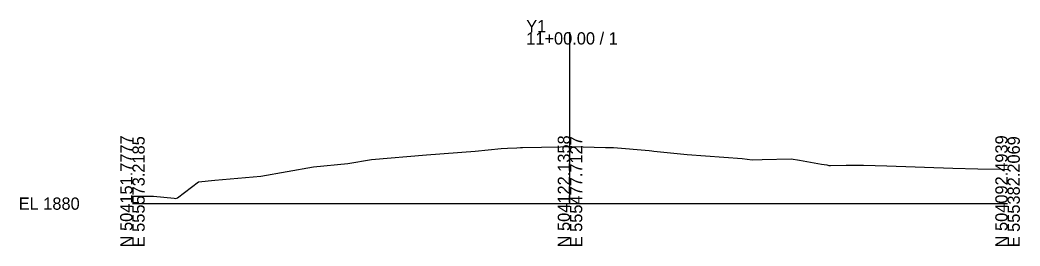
# Model space of a CAD drawing. Extents: x -26 to 203, y -10 to 5015.
# Drawn here: x -25.7 to 202.8, y 990.3 to 1042 of the extents above; entities that cross this region are included whole.
import ezdxf

# ---------------------------------------------------------------- set-up
doc = ezdxf.new("R2010")
doc.units = 0
doc.layers.add('Exist Cross Section Cell', color=7, linetype='Continuous')
doc.layers.add('Exist XS Ground Line', color=7, linetype='Continuous')

msp = doc.modelspace()

# ---------------------------------------------------------------- linework, layer by layer
at = {"layer": 'Exist Cross Section Cell'}
for p, q in [((100, 1000), (100, 1039.17)), ((0, 1000), (100, 1000)), ((100, 1000), (200, 1000))]:
    msp.add_line(p, q, dxfattribs=at)
at = {"layer": 'Exist XS Ground Line'}
for p, q in [((78.3, 1011.97), (84.28, 1012.56)), ((84.28, 1012.56), (85.71, 1012.66)), ((85.71, 1012.66), (87.83, 1012.76)), ((87.83, 1012.76), (88.72, 1012.8)), ((88.72, 1012.8), (89.18, 1012.84)), ((89.18, 1012.84), (97.85, 1012.98)), ((97.85, 1012.98), (100, 1013.05)), ((100, 1013.05), (100.39, 1013.06)), ((100.39, 1013.06), (108.14, 1012.85)), ((108.14, 1012.85), (109.96, 1012.79)), ((109.96, 1012.79), (118.13, 1012.11)), ((54.62, 1010.06), (67.24, 1011.16)), ((67.24, 1011.16), (78.3, 1011.97)), ((118.13, 1012.11), (118.69, 1012.07)), ((118.69, 1012.07), (119.17, 1012.02)), ((119.17, 1012.02), (126.78, 1011.24)), ((126.78, 1011.24), (139.32, 1010.33)), ((139.32, 1010.33), (141.66, 1010.03)), ((143.9, 1010.09), (150.54, 1010.23)), ((150.54, 1010.23), (152.42, 1009.95)), ((29.35, 1006.31), (41.39, 1008.4)), ((41.39, 1008.4), (49.22, 1009.16)), ((49.22, 1009.16), (54.62, 1010.06)), ((141.66, 1010.03), (143.9, 1010.09)), ((152.42, 1009.95), (157.47, 1009.03)), ((157.47, 1009.03), (158.7, 1008.83)), ((158.7, 1008.83), (159.19, 1008.72)), ((159.19, 1008.72), (159.56, 1008.73)), ((159.56, 1008.73), (163.11, 1008.78)), ((163.11, 1008.78), (167.07, 1008.77)), ((167.07, 1008.77), (172.41, 1008.66)), ((172.41, 1008.66), (187.49, 1008.13)), ((187.49, 1008.13), (193.19, 1007.94)), ((193.19, 1007.94), (198.46, 1007.84)), ((198.46, 1007.84), (200, 1007.81)), ((18.82, 1005.34), (29.35, 1006.31)), ((10.28, 1001.34), (15.09, 1004.94)), ((15.09, 1004.94), (18.82, 1005.34)), ((0, 1001.71), (4.84, 1001.7)), ((4.84, 1001.7), (9.55, 1001.22)), ((9.55, 1001.22), (9.89, 1001.17)), ((9.89, 1001.17), (10.28, 1001.34))]:
    msp.add_line(p, q, dxfattribs=at)

# ---------------------------------------------------------------- texts
at = {"layer": 'Exist Cross Section Cell'}
for s, p in [('Y1', (90, 1039.17)), ('11+00.00 / 1', (90, 1036.37)), ('EL 1880', (-26, 998.6))]:
    msp.add_text(s, height=2.8, dxfattribs=at).set_placement(p)
for s, p in [('N 504151.7777', (0, 990)), ('E 555573.2185', (2.8, 990)), ('N 504122.1358', (100, 990)), ('E 555477.7127', (102.8, 990)), ('N 504092.4939', (200, 990)), ('E 555382.2069', (202.8, 990))]:
    msp.add_text(s, height=2.8, rotation=90, dxfattribs=at).set_placement(p)

doc.saveas('drawing.dxf')
